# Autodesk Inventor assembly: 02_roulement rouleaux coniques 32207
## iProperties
Shininess: 60.0
Length Units: 11270
Angle Units: 11279
Time Units: 11290
Mass Units: 11283
Length Display Precision: 3
Angle Display Precision: 2
Created: 2000-10
Part Number: 02_roulement rouleaux coniques 32207
Document SubType Name: Assemblage
Density: 1.0
Volumn: 42.10969287010181
Area: 199.4189435861011
PropertySet Name: Model Information
Control State: 0
Master: False
Checked Out: False
Author: Laurent GAUTHERON
